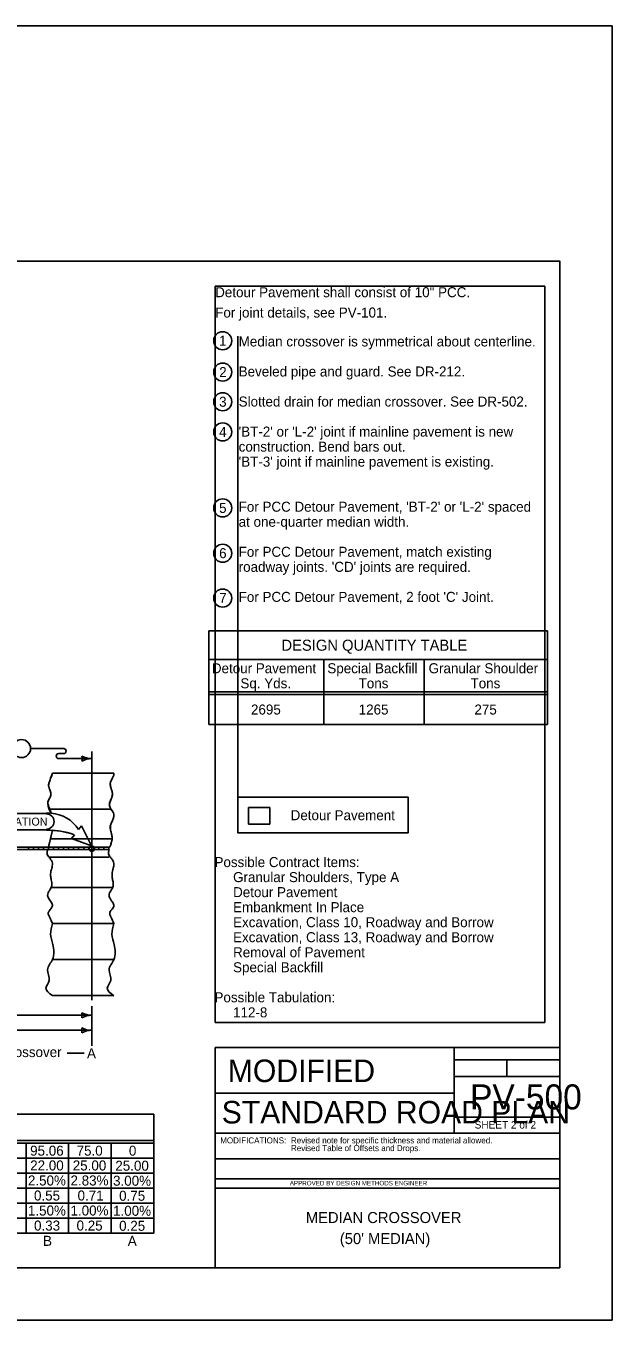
# Model space of a CAD drawing. Extents: x 10028 to 81668, y 3581 to 11018.
# Drawn here: x 15802 to 16972, y 3581 to 6165 of the extents above; entities that cross this region are included whole.
import ezdxf

# ---------------------------------------------------------------- set-up
doc = ezdxf.new("R2010")
doc.units = 0
for name, color, linetype in [('dsnCellElements', 7, 'Continuous'), ('dsnCellsNorthArrow', 7, 'Continuous'), ('DsnShtRevisedText', 7, 'Continuous'), ('dsnStdBlockModified', 7, 'Continuous'), ('dsnStdLabel', 7, 'Continuous'), ('dsnStdShading', 7, 'Continuous'), ('dsnTextFinalPlan', 7, 'Continuous'), ('dsnTextTabulation', 7, 'Continuous'), ('Level 10', 7, 'Continuous'), ('Level 11', 7, 'Continuous'), ('Level 12', 7, 'Continuous'), ('Level 6', 7, 'Continuous'), ('Level 7', 7, 'Continuous'), ('Level 8', 7, 'Continuous'), ('Level 9', 7, 'Continuous'), ('SheetAddendum', 7, 'Continuous'), ('ShtPlotIdentification', 7, 'Continuous'), ('Text', 7, 'Continuous')]:
    doc.layers.add(name, color=color, linetype=linetype)

msp = doc.modelspace()

# ---------------------------------------------------------------- linework, layer by layer
at = {"layer": 'dsnCellElements'}
msp.add_line((16166.5, 4899.9), (16843.3, 4899.9), dxfattribs=at)
at = {"layer": 'dsnCellsNorthArrow'}
for p, q in [((15932.9, 4220.2), (15932.9, 4716.6)), ((15854.6, 4301.1), (15977.4, 4301.1))]:
    msp.add_line(p, q, dxfattribs=at)
at = {"layer": 'DsnShtRevisedText'}
msp.add_lwpolyline([(13732.5, 5695.6), (16867.5, 5695.6), (16867.5, 3685.6), (13732.5, 3685.6)], close=True, dxfattribs=at)
at = {"layer": 'dsnStdLabel'}
for p, q in [((15849.9, 4592.8), (15642.4, 4592.8)), ((15851.9, 4593.3), (15842.4, 4593.7)), ((15842.4, 4593.7), (15842.4, 4591.9)), ((15849.9, 4560.3), (15642.3, 4560.3)), ((15842.4, 4561.2), (15842.4, 4559.4)), ((15898.3, 4550.1), (15892.4, 4542.8)), ((15912.4, 4567.8), (15906.8, 4560.7)), ((15932.4, 4527.8), (15912.4, 4567.8)), ((15892.4, 4542.8), (15932.4, 4527.8))]:
    msp.add_line(p, q, dxfattribs=at)
for centre, radius, start, end in [((15842.4, 4576.5), 15.3, 270, 90), ((15847.3, 4523), 70.4, 32.3953, 86.3054), ((15845.2, 4403.3), 156.1, 70.133, 91.0368)]:
    msp.add_arc(centre, radius, start, end, dxfattribs=at)
at = {"layer": 'dsnStdShading'}
for p, q in [((15977.1, 4673.1), (15854.6, 4673.1)), ((16246.2, 4604.7), (16288.9, 4604.7)), ((16246.2, 4571), (16246.2, 4604.7)), ((16288.9, 4604.7), (16288.9, 4571)), ((15854.6, 4559.1), (15846.7, 4525.5)), ((15892.4, 4542.8), (15898.3, 4550.1)), ((15906.8, 4560.7), (15912.4, 4567.8)), ((15912.4, 4567.8), (15932.4, 4527.8)), ((16288.9, 4571), (16246.2, 4571)), ((15932.4, 4527.8), (15892.4, 4542.8)), ((15854.6, 4373.1), (15977.1, 4373.1))]:
    msp.add_line(p, q, dxfattribs=at)
for points in [[(15846.7, 4525.5), (15846.9, 4525.5), (15856.9, 4525.5), (15866.9, 4525.5), (15876.9, 4525.5), (15886.9, 4525.5), (15896.9, 4525.5), (15906.9, 4525.5), (15916.9, 4525.5), (15926.9, 4525.5), (15936.9, 4525.5), (15946.9, 4525.5), (15956.9, 4525.5), (15966.9, 4525.5), (15969.2, 4525.5)], [(15967.5, 4520.7), (15966.9, 4520.7), (15956.9, 4520.7), (15946.9, 4520.7), (15936.9, 4520.7), (15926.9, 4520.7), (15916.9, 4520.7), (15906.9, 4520.7), (15896.9, 4520.7), (15886.9, 4520.7), (15876.9, 4520.7), (15866.9, 4520.7), (15856.9, 4520.7), (15846.9, 4520.7), (15845.2, 4520.7)]]:
    msp.add_lwpolyline(points, dxfattribs=at)
for centre, radius, start, end in [((15847.3, 4523), 70.4, 32.3953, 86.258), ((15845.2, 4403.3), 156.1, 70.133, 86.5437)]:
    msp.add_arc(centre, radius, start, end, dxfattribs=at)
for points in [[(15854.6, 4673.1), (15852.2, 4666.3), (15849.9, 4659.6), (15847.5, 4652.8), (15847.1, 4651.6), (15846.8, 4650.2), (15846.8, 4648.9), (15846.9, 4647.1), (15847.4, 4645.3), (15848, 4643.5), (15848.8, 4640.9), (15850, 4638.6), (15850.8, 4636), (15851.2, 4634.6), (15851.5, 4633.2), (15851.6, 4631.8), (15851.7, 4630.2), (15851.5, 4628.5), (15850.8, 4626.9), (15850, 4625.1), (15849.1, 4623.6), (15848.3, 4621.9), (15847.4, 4619.9), (15846.5, 4617.9), (15845.6, 4615.9), (15845.2, 4614.9), (15844.8, 4613.7), (15845.2, 4612.6), (15847.4, 4606.2), (15849.7, 4599.7), (15851.9, 4593.3)], [(15970.4, 4528.8), (15971, 4530.7), (15971.6, 4532.6), (15972.1, 4534.5), (15972.7, 4536.3), (15973.1, 4538.1), (15973.5, 4540), (15974, 4542.6), (15973.8, 4545.4), (15973.3, 4548.1), (15972.8, 4550.1), (15972.4, 4552.2), (15971.9, 4554.3), (15971.5, 4556.1), (15971, 4557.9), (15970.6, 4559.7), (15969.8, 4563.3), (15969.7, 4567.4), (15971.1, 4570.9), (15972.1, 4573.6), (15973.2, 4576.2), (15974.4, 4578.9), (15974.6, 4579.5), (15974.9, 4580.2), (15975.2, 4580.8), (15976, 4582.7), (15976.6, 4584.8), (15977.1, 4586.8), (15977.4, 4588.1), (15977.4, 4589.6), (15977.1, 4590.9), (15976.6, 4592.7), (15975.9, 4594.4), (15974.9, 4596), (15974, 4597.6), (15973, 4599.1), (15972, 4600.6), (15971.2, 4602.1), (15970.4, 4603.5), (15969.6, 4605), (15968.5, 4607.1), (15967.9, 4609.5), (15968.4, 4611.7), (15969.2, 4614.7), (15970.3, 4617.6), (15971.4, 4620.6), (15972, 4622.1), (15972.7, 4623.5), (15973.2, 4625), (15974.1, 4627.6), (15974.6, 4630.3), (15974.2, 4632.9), (15973.8, 4635.3), (15973.2, 4637.7), (15972.6, 4640.1), (15972.1, 4641.6), (15971.6, 4643), (15971.2, 4644.6), (15970.6, 4646.7), (15970.3, 4648.9), (15970, 4651.1), (15969.9, 4652.7), (15970.1, 4654.4), (15970.7, 4655.9), (15971.9, 4658.8), (15973.5, 4661.2), (15974.7, 4664), (15975.5, 4665.8), (15976.7, 4667.5), (15977, 4669.4), (15977.1, 4670), (15977.2, 4670.7), (15977.3, 4671.3)], [(15969.2, 4525.5), (15969.4, 4526), (15969.6, 4526.5), (15969.7, 4527), (15970, 4527.6), (15970.2, 4528.2), (15970.4, 4528.8)]]:
    msp.add_open_spline(points, degree=3, dxfattribs=at)
for points in [[(15977.3, 4671.3), (15977.3, 4672.3), (15977.2, 4672.9), (15977.1, 4673.1)], [(15845.2, 4520.7), (15843.7, 4514), (15844.3, 4510.6), (15846.7, 4506.6), (15850.7, 4501.4), (15853.9, 4496.2), (15854.5, 4490.5), (15852.4, 4480.8), (15851.1, 4474.7), (15850.8, 4469.8), (15851.7, 4462.3), (15853.3, 4452.4), (15853.2, 4448.5), (15850.8, 4442.5), (15848, 4437.8), (15846, 4434), (15844.8, 4429), (15845.7, 4425.3), (15850.6, 4417.8), (15853.3, 4413.5), (15854.5, 4409.9), (15854.1, 4406.7), (15851.4, 4402.5), (15848.7, 4399), (15847, 4396.5), (15846.2, 4394.2), (15846.2, 4392), (15847.6, 4388.7), (15850, 4383.3), (15852.8, 4377.2), (15854.6, 4373.1)], [(15977.1, 4373.1), (15971.7, 4385.1), (15969.2, 4390.8), (15968.8, 4393), (15970.6, 4397.6), (15972.3, 4400), (15975, 4403.3), (15977.1, 4407.5), (15976.7, 4411.5), (15975, 4414.9), (15971.8, 4419.4), (15968.9, 4423.9), (15967.5, 4428), (15967.8, 4431.5), (15970.1, 4436.5), (15973.6, 4442.3), (15975.1, 4445.6), (15976, 4449.7), (15975.5, 4456.2), (15974, 4464.2), (15973.5, 4468.9), (15975.2, 4480.5), (15976.8, 4487.4), (15977.2, 4492.6), (15975.7, 4497.7), (15972.3, 4502.7), (15968.7, 4507.6), (15966.8, 4511.6), (15966.5, 4514.3), (15967.5, 4520.7)]]:
    msp.add_spline(points, degree=3, dxfattribs=at)
at = {"layer": 'dsnTextFinalPlan'}
for p, q in [((15877, 4722.2), (15810.8, 4722.2)), ((15867, 4712.2), (15877, 4712.2)), ((15933.1, 4702.2), (15867, 4702.2)), ((15711.8, 4189.7), (15932.9, 4189.7)), ((15932.9, 4207.7), (15932.9, 4128.8)), ((14980, 4159.7), (15932.9, 4159.7)), ((15884.2, 4113.8), (15917.9, 4113.8))]:
    msp.add_line(p, q, dxfattribs=at)
msp.add_circle((15933.1, 4522.4), 5.33, dxfattribs=at)
for centre, radius, start, end in [((15867, 4707.2), 5, 90, 270), ((15877, 4717.2), 5, 270, 90), ((15897.4, 4702.2), 16.4, 342.2666, 17.7333), ((15933.1, 4744.7), 42.5, 241.9275, 270), ((15933.1, 4659.7), 42.5, 90, 118.0725), ((15897.3, 4189.7), 16.4, 342.2666, 17.7333), ((15932.9, 4232.2), 42.5, 241.9275, 270), ((15932.9, 4147.2), 42.5, 90, 118.0725), ((15897.3, 4159.7), 16.4, 342.2666, 17.7333), ((15932.9, 4202.2), 42.5, 241.9275, 270), ((15932.9, 4117.2), 42.5, 90, 118.0725)]:
    msp.add_arc(centre, radius, start, end, dxfattribs=at)
at = {"layer": 'dsnTextTabulation'}
for p, q in [((16396.5, 4899.9), (16396.5, 4770.2)), ((16596.5, 4899.9), (16596.5, 4770.2)), ((16166.5, 4835.2), (16843.3, 4835.2)), ((16166.5, 4830.2), (16843.3, 4830.2)), ((16246.2, 4604.7), (16288.9, 4604.7)), ((16246.2, 4571), (16246.2, 4604.7)), ((16288.9, 4604.7), (16288.9, 4571)), ((16288.9, 4571), (16246.2, 4571)), ((13812.7, 3939.4), (16056.8, 3939.4)), ((13812.7, 3934.4), (16056.8, 3934.4)), ((15801.8, 3934.4), (15801.8, 3754.4)), ((15886.8, 3934.4), (15886.8, 3754.4)), ((15971.8, 3934.4), (15971.8, 3754.4))]:
    msp.add_line(p, q, dxfattribs=at)
for centre in [(16194.5, 5536.4), (16194.5, 5473.9), (16194.5, 5414.7), (16194.5, 5354.5), (16194.5, 5202.8), (16194.5, 5112.3), (16194.5, 5022.7)]:
    msp.add_circle(centre, 18, dxfattribs=at)
at = {"layer": 'Level 10'}
msp.add_circle((15792.8, 4722.2), 18, dxfattribs=at)
at = {"layer": 'Level 11'}
for p, q in [((13812.7, 3992.4), (16056.8, 3992.4)), ((16056.8, 3992.4), (16056.8, 3754.4)), ((13812.7, 3754.4), (16056.8, 3754.4))]:
    msp.add_line(p, q, dxfattribs=at)
at = {"layer": 'Level 12'}
for p, q in [((16166.5, 4957.2), (16166.5, 4770.2)), ((16166.5, 4957.2), (16843.3, 4957.2)), ((16843.3, 4957.2), (16843.3, 4770.2)), ((16166.5, 4770.2), (16843.3, 4770.2))]:
    msp.add_line(p, q, dxfattribs=at)
msp.add_lwpolyline([(16224.5, 4624.9), (16565.1, 4624.9), (16565.1, 4554.1), (16224.5, 4554.1)], close=True, dxfattribs=at)
at = {"layer": 'Level 8'}
for p, q in [((16179.5, 5645.6), (16179.5, 4175.6)), ((16837.5, 5645.6), (16179.5, 5645.6)), ((16837.5, 5645.6), (16837.5, 4175.6)), ((16224.5, 5545.6), (16224.5, 4554.1)), ((16837.5, 4175.6), (16179.5, 4175.6))]:
    msp.add_line(p, q, dxfattribs=at)
at = {"layer": 'Level 9'}
for p, q in [((13812.7, 3904.4), (16056.8, 3904.4)), ((13812.7, 3874.4), (16056.8, 3874.4)), ((13812.7, 3844.4), (16056.8, 3844.4)), ((13812.7, 3814.4), (16056.8, 3814.4)), ((13812.7, 3784.4), (16056.8, 3784.4))]:
    msp.add_line(p, q, dxfattribs=at)
at = {"layer": 'SheetAddendum'}
for p, q in [((15854.6, 4673.1), (15977.1, 4673.1)), ((15849.2, 4601.1), (15971.8, 4601.1)), ((15846.9, 4526.1), (15854.6, 4559.1)), ((15641.2, 4525.5), (15969.2, 4525.5)), ((15806.9, 4520.7), (15806.9, 4525.5)), ((15816.9, 4520.7), (15816.9, 4525.5)), ((15826.9, 4520.7), (15826.9, 4525.5)), ((15836.9, 4520.7), (15836.9, 4525.5)), ((15846.9, 4520.7), (15846.9, 4525.5)), ((15850.2, 4541.9), (15972.9, 4541.9)), ((15856.9, 4520.7), (15856.9, 4525.5)), ((15866.9, 4520.7), (15866.9, 4525.5)), ((15876.9, 4520.7), (15876.9, 4525.5)), ((15886.9, 4520.7), (15886.9, 4525.5)), ((15896.9, 4520.7), (15896.9, 4525.5)), ((15906.9, 4520.7), (15906.9, 4525.5)), ((15916.9, 4520.7), (15916.9, 4525.5)), ((15926.9, 4520.7), (15926.9, 4525.5)), ((15936.9, 4520.7), (15936.9, 4525.5)), ((15946.9, 4520.7), (15946.9, 4525.5)), ((15956.9, 4520.7), (15956.9, 4525.5)), ((15966.9, 4520.7), (15966.9, 4525.5)), ((15641.2, 4520.7), (15967.4, 4520.7)), ((15848.7, 4505.1), (15967.5, 4505.1)), ((15852.1, 4445.1), (15974, 4445.1)), ((15854.6, 4373.1), (15977.1, 4373.1)), ((15854.6, 4229.1), (15976.9, 4229.1))]:
    msp.add_line(p, q, dxfattribs=at)
for points in [[(15851.9, 4593.2), (15845.2, 4612.6), (15845.6, 4615.9), (15848.3, 4621.9), (15850.8, 4626.9), (15851.6, 4631.8), (15850.8, 4636), (15848, 4643.5), (15846.8, 4648.9), (15847.5, 4652.8), (15854.6, 4673.1)], [(15977.3, 4671.3), (15977, 4669.4), (15974.7, 4664), (15970.7, 4655.9), (15970, 4651.1), (15971.2, 4644.6), (15972.6, 4640.1), (15974.2, 4632.9), (15973.2, 4625), (15971.4, 4620.6), (15968.4, 4611.7), (15969.6, 4605), (15972, 4600.6), (15974.9, 4596), (15977.1, 4590.9), (15977.1, 4586.8), (15975.2, 4580.8), (15974.4, 4578.9), (15971.1, 4570.9), (15970.6, 4559.7), (15971.9, 4554.3), (15973.3, 4548.1), (15973.5, 4540), (15972.1, 4534.5), (15970.4, 4528.7)], [(15977.3, 4671.2), (15977.3, 4672.3), (15977.2, 4672.9), (15977.1, 4673.1)], [(15970.4, 4528.8), (15969.7, 4527), (15969.2, 4525.5)], [(15845.2, 4520.7), (15843.7, 4514), (15844.3, 4510.6), (15846.7, 4506.6), (15850.7, 4501.4), (15853.9, 4496.2), (15854.5, 4490.5), (15852.4, 4480.8), (15851.1, 4474.7), (15850.8, 4469.8), (15851.7, 4462.3), (15853.3, 4452.4), (15853.2, 4448.5), (15850.8, 4442.5), (15848, 4437.8), (15846, 4434), (15844.8, 4429), (15845.7, 4425.3), (15850.6, 4417.8), (15853.3, 4413.5), (15854.5, 4409.9), (15854.1, 4406.7), (15851.4, 4402.5), (15848.7, 4399), (15847, 4396.5), (15846.2, 4394.2), (15846.2, 4392), (15847.6, 4388.7), (15850, 4383.3), (15852.8, 4377.2), (15854.6, 4373.1)], [(15977.1, 4373.1), (15971.7, 4385.1), (15969.2, 4390.8), (15968.8, 4393), (15970.6, 4397.6), (15972.3, 4400), (15975, 4403.3), (15977.1, 4407.5), (15976.7, 4411.5), (15975, 4414.9), (15971.8, 4419.4), (15968.9, 4423.9), (15967.5, 4428), (15967.8, 4431.5), (15970.1, 4436.5), (15973.6, 4442.3), (15975.1, 4445.6), (15976, 4449.7), (15975.5, 4456.2), (15974, 4464.2), (15973.5, 4468.9), (15975.2, 4480.5), (15976.8, 4487.4), (15977.2, 4492.6), (15975.7, 4497.7), (15972.3, 4502.7), (15968.7, 4507.6), (15966.8, 4511.6), (15966.5, 4514.3), (15967.5, 4520.7)], [(15854.6, 4373.1), (15850.8, 4351.9), (15855.1, 4331.3), (15854.6, 4301.1), (15844.8, 4280.8), (15848.2, 4259.4), (15841.4, 4244), (15854.6, 4229.1)], [(15977.1, 4373.1), (15973.4, 4351.5), (15977.7, 4331), (15977.2, 4300.7), (15967.5, 4280.4), (15970.9, 4259), (15964, 4243.6), (15977.2, 4228.7)]]:
    msp.add_spline(points, degree=3, dxfattribs=at)
at = {"layer": 'ShtPlotIdentification'}
msp.add_lwpolyline([(13628, 3581.1), (16972, 3581.1), (16972, 6165.1), (13628, 6165.1)], close=True, dxfattribs=at)
at = {"layer": 'Text'}
for p, q in [((16656.6, 4125.6), (16656.6, 4034.3)), ((16656.6, 4100.7), (16867.5, 4100.7)), ((16762.1, 4100.7), (16762.1, 4067.5)), ((16656.6, 4067.5), (16867.5, 4067.5)), ((16179.5, 4034.3), (16656.6, 4034.3)), ((16656.6, 4034.3), (16656.6, 3954.3)), ((16867.5, 3986.5), (16656.6, 3986.5)), ((16179.5, 3954.3), (16867.5, 3954.3)), ((16179.5, 3903.3), (16867.5, 3903.3)), ((16179.5, 3863.3), (16867.5, 3863.3)), ((16179.5, 3844.3), (16867.5, 3844.3))]:
    msp.add_line(p, q, dxfattribs=at)
msp.add_lwpolyline([(16179.5, 4125.6), (16867.5, 4125.6), (16867.5, 3685.6), (16179.5, 3685.6)], close=True, dxfattribs=at)

# ---------------------------------------------------------------- texts
at = {"layer": 'dsnCellElements'}
for s, height, p in [('Detour Pavement shall consist of 10" PCC.', 20, (16179.5, 5623.4)), ('For joint details, see PV-101.', 20, (16179.5, 5582.8)), ('1', 20, (16187, 5526.4)), ('Median crossover is symmetrical about centerline.', 20, (16226.4, 5525.1)), ('2', 20, (16187.5, 5463.9)), ('Beveled pipe and guard. See DR-212.', 20, (16226.4, 5465.1)), ('3', 20, (16187.4, 5404.7)), ('Slotted drain for median crossover. See DR-502.', 20, (16226.4, 5405.1)), ('4', 20, (16187.4, 5344.5)), ("'BT-2' or 'L-2' joint if mainline pavement is new  ", 20, (16226.4, 5345.1)), ('construction. Bend bars out.', 20, (16226.4, 5315.1)), ("'BT-3' joint if mainline pavement is existing. ", 20, (16226.4, 5285.1)), ('5', 20, (16187.3, 5192.8)), ("For PCC Detour Pavement, 'BT-2' or 'L-2' spaced ", 20, (16226.4, 5195.1)), ('at one-quarter median width.', 20, (16226.4, 5165.1)), ('6', 20, (16187.4, 5102.3)), ('For PCC Detour Pavement, match existing ', 20, (16226.4, 5105.1)), ("roadway joints. 'CD' joints are required. ", 20, (16226.4, 5075.1)), ('7', 20, (16187.4, 5012.7)), ("For PCC Detour Pavement, 2 foot 'C' Joint.", 20, (16226.4, 5015.1)), ('Possible Contract Items:', 20, (16178.1, 4485.6)), ('     Granular Shoulders, Type A', 20, (16178.1, 4455.6)), ('     Detour Pavement', 20, (16178.1, 4425.6)), ('     Embankment In Place', 20, (16178.1, 4395.6)), ('     Excavation, Class 10, Roadway and Borrow', 20, (16178.1, 4365.6)), ('     Excavation, Class 13, Roadway and Borrow', 20, (16178.1, 4335.6)), ('     Removal of Pavement', 20, (16178.1, 4305.6)), ('     Special Backfill', 20, (16178.1, 4275.6)), ('Possible Tabulation:', 20, (16178.1, 4215.6)), ('     112-8', 20, (16178.1, 4185.6)), ('MODIFICATIONS:', 12, (16189.5, 3933.9)), ('Revised note for specific thickness and material allowed.', 12, (16330.8, 3934)), ('Revised Table of Offsets and Drops.', 12, (16330.8, 3918.5)), ('2.50%', 20, (15805.6, 3849.9)), ('2.83%', 20, (15890.6, 3849.9)), ('3.00%', 20, (15975.6, 3849.4)), ('0.55', 20, (15817.7, 3819.9)), ('0.71', 20, (15904.7, 3819.9)), ('0.75', 20, (15987.7, 3819.4)), ('1.50%', 20, (15805.6, 3789.9)), ('1.00%', 20, (15890.6, 3789.9)), ('1.00%', 20, (15975.6, 3789.4)), ('0.33', 20, (15817.8, 3759.9)), ('0.25', 20, (15902.7, 3759.9)), ('0.25', 20, (15987.7, 3759.4))]:
    msp.add_text(s, height=height, dxfattribs=at).set_placement(p)
at = {"layer": 'dsnStdBlockModified'}
msp.add_text('MODIFIED', height=45, dxfattribs=at).set_placement((16204.6, 4056.4))
at = {"layer": 'dsnStdLabel'}
msp.add_text('LOCATION STATION', height=16, dxfattribs=at).set_placement((15636.6, 4568.4))
at = {"layer": 'Level 6'}
for s, p in [('Detour Pavement', (16172.9, 4872.6)), ('Special Backfill', (16403.5, 4872.6)), ('Granular Shoulder', (16605.6, 4872.6)), ('Sq. Yds.', (16229.9, 4842.6)), ('Tons', (16465.9, 4842.6)), ('Tons', (16689.4, 4842.6)), ('2695', (16251, 4790.2)), ('1265', (16466, 4790.2)), ('275', (16697.1, 4790.2)), ('Detour Pavement', (16330.2, 4579.2)), (' of Crossover', (15713.8, 4106.3)), ('A', (15923.6, 4103.8)), ('95.06', (15810, 3909.4)), ('75.0', (15902.8, 3909.4)), ('0', (16007.2, 3909.4)), ('22.00', (15810.1, 3879.9)), ('25.00', (15895.1, 3879.9)), ('25.00', (15980.1, 3879.4)), ('B', (15835.8, 3729.4)), ('A', (16005, 3729.4))]:
    msp.add_text(s, height=20, dxfattribs=at).set_placement(p)
at = {"layer": 'Level 7'}
msp.add_text('DESIGN QUANTITY TABLE', height=22, dxfattribs=at).set_placement((16311.8, 4917.6))
at = {"layer": 'Text'}
for s, height, p in [('PV-500', 50, (16688.4, 4001.8)), ('STANDARD ROAD PLAN', 45.001, (16192.5, 3973.7)), ('SHEET 2 of 2', 15, (16697.6, 3963.6)), ('APPROVED BY DESIGN METHODS ENGINEER', 9.003, (16328.5, 3850.1)), ('MEDIAN CROSSOVER', 22, (16360.5, 3774.9)), ("(50' MEDIAN)", 22, (16428.4, 3732.9))]:
    msp.add_text(s, height=height, dxfattribs=at).set_placement(p)

doc.saveas('drawing.dxf')
